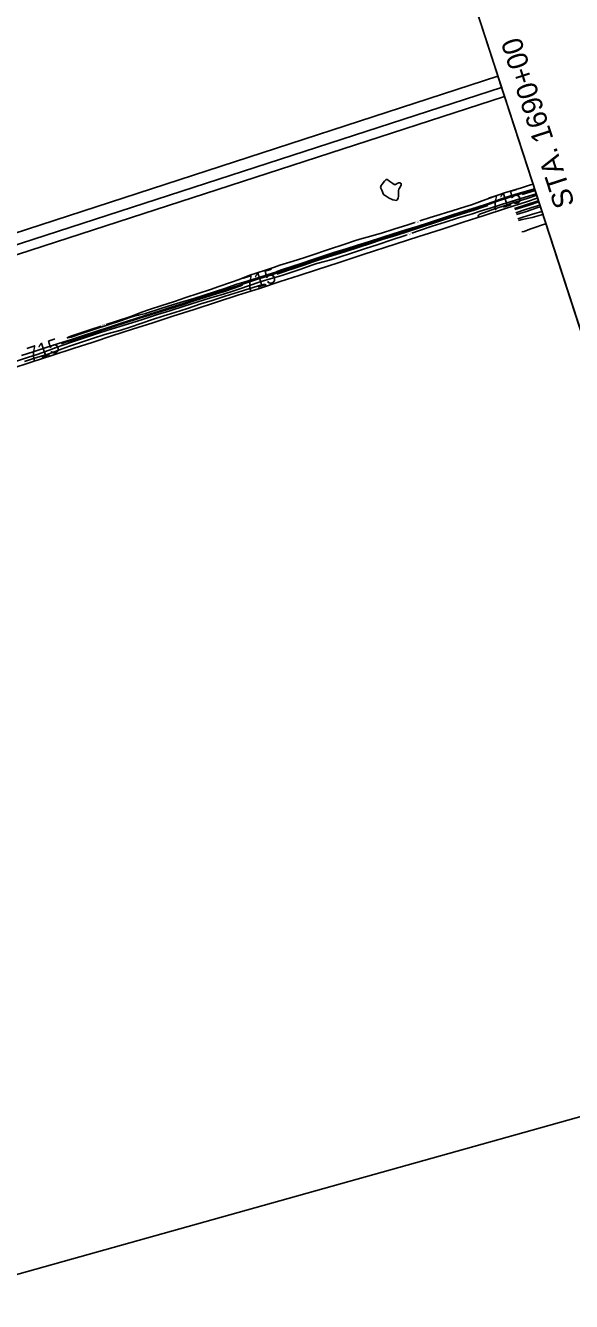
# Model space of a CAD drawing. Extents: x -468556195 to 3353078, y -306091294 to 1252632.
# Drawn here: x 1833652 to 1834891, y 532729 to 535626 of the extents above; entities that cross this region are included whole.
import ezdxf

# ---------------------------------------------------------------- set-up
doc = ezdxf.new("R2010")
doc.units = 0
for name, color, linetype in [('Default', 7, 'Continuous'), ('DT_X_Contour_Minor', 7, 'Continuous'), ('DT_X_Terrain_Ground_Line', 7, 'Continuous'), ('Level 14', 7, 'Continuous'), ('Level 19', 7, 'Continuous'), ('SC_Scratch1', 7, 'Continuous'), ('SC_Shading3', 7, 'Continuous')]:
    doc.layers.add(name, color=color, linetype=linetype)

msp = doc.modelspace()

# ---------------------------------------------------------------- linework, layer by layer
at = {"layer": 'Default'}
msp.add_lwpolyline([(1827117.1, 533034.5), (1827123.3, 533015.5), (1834732.4, 535485.8), (1834724, 535511.6)], close=True, dxfattribs=at)
at = {"layer": 'DT_X_Contour_Minor'}
for points in [[(1834485.4, 535230.6), (1834490.1, 535229.6), (1834493.5, 535229.3), (1834494.7, 535229.7), (1834495.6, 535230.4), (1834497.1, 535232.6), (1834497.9, 535235.1), (1834498.3, 535238.1), (1834498.7, 535251.7), (1834499.4, 535254.6), (1834500.4, 535257), (1834503.5, 535262.1), (1834504.1, 535264.7), (1834504.3, 535266.7), (1834504.1, 535267.5), (1834503.5, 535268.1), (1834502.7, 535268.6), (1834501.7, 535268.9), (1834499.4, 535268.8), (1834496.6, 535268.3), (1834491.6, 535265.6), (1834488.9, 535265.7), (1834485.6, 535267.3), (1834479.1, 535272.4), (1834475.2, 535275.2), (1834472.4, 535276.6), (1834471.3, 535276.6), (1834469.8, 535276.2), (1834467.9, 535274.8), (1834466.5, 535273.3), (1834461.1, 535266.2), (1834459.2, 535263.4), (1834458, 535261.1), (1834457.7, 535259.2), (1834458.1, 535257.2), (1834460.5, 535252.5), (1834462.3, 535248.9), (1834462.8, 535246.5), (1834463.4, 535244.1), (1834464, 535243.2), (1834464.9, 535242.2), (1834467.8, 535240.1), (1834477.5, 535234.4), (1834484, 535231.2), (1834485.4, 535230.6)], [(1834546.9, 535182.7), (1834570.1, 535190.1), (1834592.8, 535197.4), (1834607, 535201.7), (1834619.8, 535205.3), (1834636.8, 535210.6), (1834649.2, 535214.6), (1834663.7, 535219.4), (1834688.2, 535228), (1834715.2, 535237.9), (1834738.7, 535246.1), (1834751.9, 535250.3), (1834777.5, 535257.8), (1834797.9, 535264.4), (1834803.6, 535266.2)], [(1834807, 535255.8), (1834796.4, 535252.5), (1834762.1, 535242.5), (1834748, 535238.3), (1834729.9, 535232), (1834700.2, 535221.7), (1834674.8, 535213.5), (1834649.7, 535205.5), (1834621.1, 535196.2), (1834596, 535188), (1834566.5, 535178.3), (1834540.7, 535170.2), (1834514.9, 535162.1), (1834486.2, 535153.1), (1834460.6, 535145), (1834430.4, 535135.5), (1834405.1, 535127.5), (1834379.8, 535119.5), (1834351.4, 535110.8), (1834335.8, 535105.8), (1834303.9, 535094.7), (1834280, 535086.7), (1834256.6, 535079.2), (1834235.1, 535072.4), (1834225, 535068.6), (1834220, 535066.6), (1834203.1, 535061), (1834177, 535052.8), (1834147.9, 535043.9), (1834131.9, 535038.7), (1834104.6, 535029.4), (1834083.1, 535022.1), (1834057.2, 535013.8), (1834034.2, 535006.6), (1834003.3, 534997.4), (1833978.1, 534989.6), (1833956.8, 534982.8), (1833924.1, 534972.6), (1833908.7, 534968.3), (1833899.1, 534966), (1833889.2, 534963.1), (1833867.4, 534956)], [(1834176.6, 535049.4), (1834208.9, 535059.8), (1834232.5, 535067.5), (1834237.2, 535069.5), (1834239.9, 535070.7), (1834244.4, 535072.5), (1834260.5, 535077.7), (1834285.1, 535085.6), (1834308.3, 535093.6), (1834331.6, 535101.6), (1834350.6, 535107.5), (1834382.2, 535117.4), (1834412.2, 535126.9), (1834440.6, 535136.1), (1834472.6, 535146.2), (1834502.4, 535155.7), (1834530.9, 535164.7), (1834556.2, 535172.8), (1834583.9, 535182), (1834613.4, 535191.6), (1834636.9, 535199.2), (1834664.8, 535208), (1834696, 535218), (1834725.1, 535228.1), (1834746.3, 535235.2), (1834765.2, 535241.1), (1834789.5, 535248.1), (1834807.6, 535253.6), (1834807.7, 535253.6)], [(1834810.7, 535244.4), (1834810.7, 535244.4), (1834785.7, 535236.6), (1834753.6, 535226.9), (1834732.4, 535220.2), (1834706.1, 535212), (1834683.7, 535204.7), (1834666.3, 535199.1), (1834634.3, 535189.7), (1834604.3, 535180.1), (1834575, 535170.5), (1834544.1, 535159.9), (1834528.7, 535154.7)], [(1834679.4, 535191.1), (1834679.4, 535191.2), (1834679.1, 535193.3), (1834679.8, 535195.4), (1834681.6, 535197), (1834684.2, 535198.4), (1834693.2, 535201.6), (1834716.2, 535209.8), (1834733.8, 535215.7), (1834757.9, 535223.4), (1834790.4, 535233.9), (1834811.9, 535240.9)], [(1834779.3, 535242.8), (1834805.8, 535250.7), (1834808.4, 535251.6)], [(1834222.2, 535061.6), (1834240.4, 535067.6), (1834248.6, 535070.5), (1834254, 535072.7), (1834281.1, 535081.5), (1834307.3, 535090.6), (1834327.5, 535097.5), (1834356.8, 535106.4), (1834378.8, 535113.3), (1834408.9, 535123.1), (1834432.3, 535130.7), (1834461.7, 535140.1), (1834492.2, 535149.9), (1834522.4, 535159.6), (1834551.8, 535169.1), (1834582.2, 535179.4), (1834611.5, 535188.9), (1834640.4, 535198.2), (1834670.4, 535207.4), (1834691.7, 535214.4), (1834701.3, 535217.7)], [(1834816, 535228.2), (1834815.5, 535228.1), (1834784.8, 535218.2), (1834761.9, 535210.7)], [(1834816.8, 535225.7), (1834792.6, 535217.9), (1834762.6, 535208.3)], [(1834819.1, 535218.7), (1834808.1, 535215.4), (1834784.1, 535207.6), (1834764.8, 535201.3)], [(1834820.4, 535214.6), (1834814.7, 535212.8), (1834788.7, 535204.3), (1834766.1, 535197.2)], [(1834823.8, 535204.1), (1834808, 535199.4), (1834780.8, 535191), (1834769.2, 535187.3)], [(1833835.1, 534947.5), (1833858.3, 534955.2), (1833888.9, 534965.2), (1833900.7, 534969.6), (1833913.5, 534974.5), (1833935.6, 534982.2), (1833958.9, 534989.9), (1833990.2, 535000), (1834015.6, 535008.7), (1834043.7, 535018.2), (1834071.6, 535027.1), (1834090.6, 535033.5), (1834119.3, 535043.3), (1834136.9, 535049.7), (1834161.5, 535059.2), (1834175.3, 535064.1), (1834199, 535071.7), (1834217.4, 535077.9), (1834229.5, 535082), (1834259.1, 535091.1), (1834283.5, 535098.7), (1834308.3, 535106.9), (1834330.5, 535114.5), (1834355.3, 535123.3), (1834361.1, 535124.8), (1834374.2, 535129.2), (1834400.5, 535138.2), (1834416.2, 535143.1), (1834430.2, 535146.9), (1834443, 535150), (1834460.1, 535155), (1834487.9, 535163.7), (1834519.5, 535173.7), (1834535.5, 535179)], [(1834770.3, 535183.8), (1834770.5, 535183.8), (1834778.8, 535186), (1834801.3, 535190.7), (1834822.8, 535196.5), (1834826, 535197.3)], [(1834832.8, 535176.3), (1834825, 535173.7), (1834807.5, 535167.9), (1834796, 535163.6), (1834783.8, 535158.9), (1834778.5, 535157.9)], [(1834517.3, 535150.9), (1834513.4, 535149.6), (1834483.5, 535139.7), (1834452.6, 535129.4), (1834421.3, 535119), (1834389.7, 535108.7), (1834365.9, 535101), (1834350, 535096), (1834333.4, 535091.3), (1834312.9, 535085.9), (1834301.7, 535082.1), (1834274.8, 535072.4), (1834256.3, 535066.1), (1834234.1, 535059.1), (1834207, 535051.2), (1834187.2, 535045.2), (1834157.9, 535035.6), (1834138.7, 535028.8), (1834122.9, 535023.2), (1834101.3, 535016.7), (1834069.3, 535007), (1834043.5, 534999), (1834011.8, 534988.9), (1833979.4, 534978.6), (1833952, 534969.9), (1833920.2, 534959.7), (1833893.2, 534951.1), (1833866.4, 534942.6), (1833836.9, 534933.6), (1833817.5, 534927.4), (1833786.4, 534917), (1833756.5, 534907), (1833721.9, 534895.5), (1833705.6, 534889.5), (1833678.5, 534879.6), (1833656.4, 534872.3), (1833622.6, 534861.4)], [(1833642.8, 534876.9), (1833669.9, 534885.6), (1833699.3, 534895.1), (1833725.2, 534903.3), (1833756.7, 534913.2), (1833783.9, 534922.4), (1833811.6, 534931.7), (1833842, 534941.6), (1833868.9, 534950.3), (1833900.1, 534960.5), (1833925.8, 534968.5), (1833953, 534977.1), (1833982.4, 534986.6), (1834010.1, 534995.3), (1834042.6, 535005.5), (1834068.6, 535013.8), (1834097, 535022.8), (1834126, 535032.8), (1834144.6, 535039), (1834176.6, 535049.4)], [(1833734.1, 534903.8), (1833741.7, 534906.3), (1833764.4, 534913.7), (1833791.1, 534922.7), (1833822.3, 534933.1), (1833854.7, 534943.4), (1833878.7, 534951.2), (1833908.8, 534960.9), (1833933.7, 534968.7), (1833964.2, 534978.4), (1833989.3, 534986.4), (1834012.7, 534993.8), (1834037.5, 535001.7), (1834061.1, 535009.4), (1834085.3, 535016.9), (1834101.2, 535021.8), (1834125.6, 535030.1), (1834144.5, 535036.4)], [(1833889.3, 534941.5), (1833915.9, 534950.6), (1833937.7, 534957.8), (1833966, 534966.8), (1833990.7, 534974.7), (1834019.8, 534984), (1834050.2, 534994.1), (1834075.4, 535002.1), (1834105.5, 535011.8), (1834134.3, 535020.7), (1834161.5, 535029.2), (1834188.3, 535037.5), (1834191.9, 535038.3), (1834194.8, 535038.6), (1834196.5, 535038.3), (1834197.4, 535037.3), (1834198.5, 535034.8)], [(1833867.4, 534956), (1833839.7, 534946.9), (1833807.1, 534936.3), (1833782.4, 534928), (1833755.5, 534919), (1833748.5, 534917.3), (1833746.8, 534917.2), (1833749.6, 534918.5), (1833755, 534920.7), (1833773.4, 534927), (1833800.4, 534936.2), (1833823.7, 534943.8)], [(1833649.7, 534863.7), (1833670.5, 534870.1), (1833702.7, 534880.2), (1833713.5, 534883.8), (1833735.1, 534892.1), (1833751.8, 534898.1), (1833775, 534905.8), (1833806.7, 534916.4), (1833829.6, 534924.1), (1833837.4, 534926.5), (1833866.1, 534934), (1833889.3, 534941.5)]]:
    msp.add_lwpolyline(points, dxfattribs=at)
at = {"layer": 'DT_X_Terrain_Ground_Line'}
msp.add_line((1835055.9, 534489.2), (1834448.3, 536360.7), dxfattribs=at)
at = {"layer": 'Level 14'}
msp.add_lwpolyline([(1834813.2, 535234.2), (1834790.9, 535227), (1834741.2, 535210.8), (1834693, 535195.2), (1834645.2, 535179.5), (1834595.1, 535163.3), (1834544.7, 535147.1), (1834493.2, 535130.4), (1834418.6, 535106.4), (1834363.9, 535088.5), (1834312.7, 535071.9), (1834273, 535059), (1834229.8, 535044.8), (1834182.9, 535029.5), (1834134.2, 535013.7), (1834085.3, 534998), (1834034.9, 534981.8), (1833986.3, 534966.1), (1833940.8, 534951.5), (1833895, 534936.5), (1833848.3, 534921.4), (1833805.5, 534907.4), (1833760.6, 534892.6), (1833714.5, 534877.7), (1833665, 534861.6), (1833618.7, 534846.6)], dxfattribs=at)
at = {"layer": 'SC_Scratch1'}
msp.add_lwpolyline([(1826839.3, 533890.1), (1826769.8, 534863.1), (1833950.4, 537284.3), (1834448.3, 536360.7), (1835055.9, 534489.2), (1835128.1, 533209.3), (1827818.5, 531160.4), (1827446.8, 532019.1)], close=True, dxfattribs=at)
at = {"layer": 'SC_Shading3'}
msp.add_lwpolyline([(1827130.1, 532994.6), (1827117.1, 533034.5), (1834724, 535511.6), (1834739.2, 535464.9)], close=True, dxfattribs=at)

# ---------------------------------------------------------------- texts
at = {"layer": 'DT_X_Terrain_Ground_Line'}
msp.add_text('MATCH LINE                   STA. 1690+00', height=46.8, rotation=107.9864, dxfattribs=at).set_placement((1835117.7, 534546))
at = {"layer": 'Level 19'}
for s, height, rotation, p in [('715', 33, 17.1257, (1834709.8, 535204)), ('713', 4, 17.6471, (1834536.8, 535177.4)), ('717', 4, 18.4893, (1834518.6, 535149.3)), ('715', 33, 17.8075, (1834153.5, 535022.1)), ('713', 4, 18.1341, (1833825, 534942.2)), ('715', 33, 18.879, (1833663.1, 534862.6))]:
    msp.add_text(s, height=height, rotation=rotation, dxfattribs=at).set_placement(p)

doc.saveas('drawing.dxf')
